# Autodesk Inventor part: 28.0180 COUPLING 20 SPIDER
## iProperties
Created: 2007-06
Part Number: 28.0180 COUPLING 20 SPIDER
Material: Rubber
Document SubType Name: Modeling
Designer: Andy Moles
Mass: 18.0274 g
Surface Area: 79.417 cm^2
Volume: 19.3842 cm^3
Density: 0.93 g/cm^3
Author: Andy Moles
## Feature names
1. Base1
